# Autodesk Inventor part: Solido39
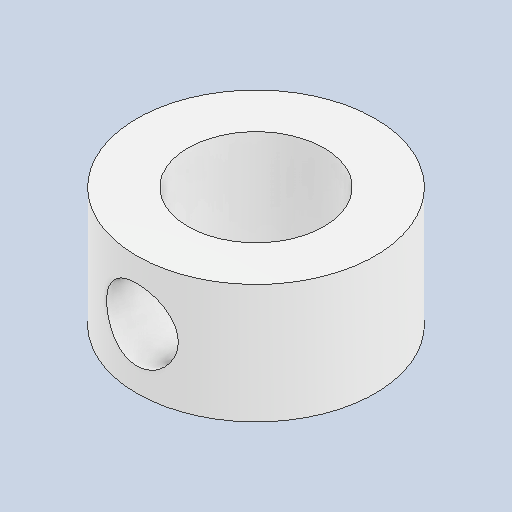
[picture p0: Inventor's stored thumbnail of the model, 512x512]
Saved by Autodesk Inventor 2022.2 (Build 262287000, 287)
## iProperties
Created: 2024-10
Part Number: Solido39
Material: Generico
Document SubType Name: Modeling
Designer: 18907419
Density: 1 g/cm^3
Appearance: Default
Author: 18907419
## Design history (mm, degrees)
feature "Solido39"
node "Solido1"
